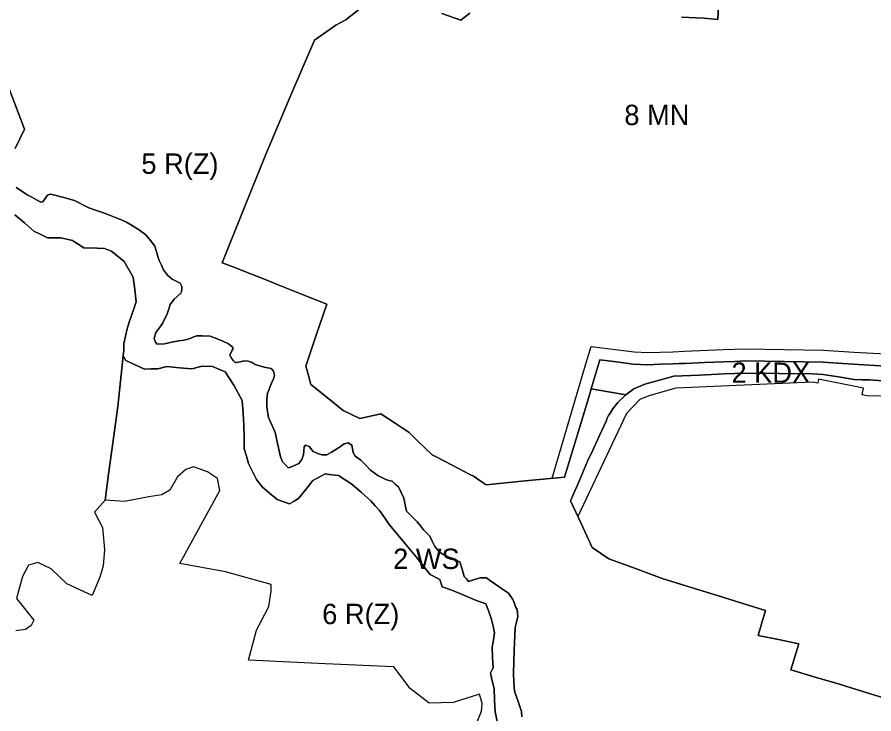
# Model space of a CAD drawing. Extents: x -294445 to -292055, y 21869 to 23693.
# Drawn here: x -293995.9 to -293575, y 22129.5 to 22471.6 of the extents above; entities that cross this region are included whole.
import ezdxf

# ---------------------------------------------------------------- set-up
doc = ezdxf.new("R2010")
doc.units = 0
for name, color, linetype in [('linie_rozgraniczajace', 7, 'Continuous'), ('linie_zabudowy_nieprzekraczalne', 7, 'Continuous'), ('oznaczenia_przeznaczen', 7, 'Continuous')]:
    doc.layers.add(name, color=color, linetype=linetype)

msp = doc.modelspace()

# ---------------------------------------------------------------- linework, layer by layer
at = {"layer": 'linie_rozgraniczajace'}
for points in [[(-293669.485, 22471.61), (-293662.035, 22471.25), (-293658.31, 22471.07), (-293651.55, 22470.39), (-293650.913, 22483.44)], [(-293650.913, 22483.44), (-293651.55, 22470.39), (-293658.31, 22471.07), (-293662.035, 22471.25), (-293669.485, 22471.61)], [(-293895.099, 22350.989), (-293884.475, 22377.411), (-293873.851, 22403.833), (-293861.856, 22432.017), (-293849.86, 22460.2), (-293839.31, 22467.62), (-293834.33, 22470.28), (-293823.35, 22478.86)], [(-293823.35, 22478.86), (-293834.33, 22470.28), (-293839.31, 22467.62), (-293849.86, 22460.2), (-293861.856, 22432.017), (-293873.851, 22403.833), (-293884.475, 22377.411), (-293895.099, 22350.989), (-293888.998, 22348.592), (-293882.896, 22346.194), (-293875.674, 22343.307), (-293868.451, 22340.419), (-293856.133, 22335.494), (-293843.814, 22330.57), (-293848.947, 22315.346), (-293854.08, 22300.122), (-293852.804, 22295.615), (-293851.529, 22291.107), (-293843.613, 22284.726), (-293835.696, 22278.345), (-293831.615, 22276.438), (-293827.535, 22274.532), (-293822.327, 22275.651), (-293817.12, 22276.77), (-293810.2, 22272.17), (-293803.28, 22267.57), (-293799.36, 22263.72), (-293791.97, 22256.66), (-293789.09, 22255.16), (-293786.21, 22253.66), (-293778.755, 22249.805), (-293773.734, 22247.209), (-293771.3, 22245.95), (-293768.39, 22243.92), (-293765.48, 22241.89), (-293746.225, 22243.815), (-293726.97, 22245.74), (-293721.229, 22264.536), (-293715.487, 22283.331), (-293714.654, 22286.159), (-293713.821, 22288.988), (-293696.76, 22286.12), (-293700.82, 22282.26), (-293701.99, 22280.77), (-293703.16, 22279.28), (-293704.235, 22277.645), (-293705.31, 22276.01), (-293705.935, 22274.63), (-293706.56, 22273.25), (-293709.81, 22266.105), (-293713.06, 22258.96), (-293715.62, 22253.54), (-293719.8, 22243.785), (-293723.98, 22234.03), (-293718.67, 22222.545), (-293713.36, 22211.06)], [(-293787.308, 22473.333), (-293777.927, 22469.988), (-293773.45, 22473.55)], [(-293773.45, 22473.55), (-293777.927, 22469.988), (-293787.308, 22473.333)], [(-293996.895, 22407.1), (-293992.35, 22416.5), (-294000.24, 22437.73)], [(-294000.24, 22437.73), (-293992.35, 22416.5), (-293996.895, 22407.1)], [(-293967.78, 22381.47), (-293972.925, 22382.925), (-293978.07, 22384.38), (-293979.68, 22384.64), (-293980.99, 22384.14), (-293983.19, 22380.88), (-293984.21, 22380.78), (-293986.3, 22381.85), (-293988.6, 22383.115), (-293990.9, 22384.38), (-293993.655, 22386.175), (-293996.41, 22387.97)], [(-293996.41, 22387.97), (-293993.655, 22386.175), (-293990.9, 22384.38), (-293988.6, 22383.115), (-293986.3, 22381.85), (-293984.21, 22380.78), (-293983.19, 22380.88), (-293980.99, 22384.14), (-293979.68, 22384.64), (-293978.07, 22384.38), (-293972.925, 22382.925), (-293967.78, 22381.47), (-293960.65, 22377.98), (-293956.825, 22376.64), (-293953, 22375.3), (-293950.51, 22374.355), (-293948.02, 22373.41), (-293945.055, 22372.135), (-293942.09, 22370.86), (-293938.91, 22368.895), (-293935.73, 22366.93), (-293932.72, 22364.71), (-293930.45, 22361.87)], [(-293845.96, 22256.68), (-293847.85, 22257.1), (-293850.38, 22258.35), (-293852.46, 22260.67), (-293854.15, 22261.33), (-293854.92, 22260.61), (-293855.04, 22258.645), (-293855.16, 22256.68), (-293856.01, 22254.27), (-293857.5, 22252.45), (-293861.13, 22250.73), (-293862.74, 22250.27), (-293864.095, 22251.76), (-293865.45, 22253.25), (-293866.54, 22255.6), (-293867.81, 22261.63), (-293869.08, 22267.66), (-293870.76, 22271.315), (-293872.44, 22274.97), (-293872.826, 22277.985), (-293873.15, 22280.51), (-293873.145, 22282.005), (-293873.14, 22283.5), (-293872.81, 22286.84), (-293872.271, 22288.356), (-293871.534, 22290.215), (-293870.91, 22291.77), (-293869.96, 22293.94), (-293869.5, 22295.72), (-293869.93, 22297.66), (-293871.07, 22299.02), (-293874.55, 22299.68), (-293878.89, 22300.93), (-293880.43, 22302), (-293882.35, 22302.68), (-293884.33, 22302.8), (-293886.235, 22302.365), (-293888.14, 22301.93), (-293888.82, 22302.02), (-293889.62, 22302.75), (-293890.537, 22304.187), (-293891.454, 22305.624), (-293890.27, 22307.97), (-293889.78, 22308.82), (-293890.32, 22309.72), (-293892.06, 22311.16), (-293894.835, 22312.41), (-293897.61, 22313.66), (-293901.08, 22314.97), (-293904.95, 22315.15), (-293907.57, 22315), (-293909.03, 22314.59), (-293911.3, 22313.6), (-293913.77, 22313.02), (-293916.48, 22312.67), (-293919.945, 22311.905), (-293923.41, 22311.14), (-293927.04, 22310.97), (-293927.99, 22311.92), (-293928.3, 22312.86), (-293928.61, 22313.8), (-293927.7, 22316.67), (-293926.06, 22318.89), (-293924.42, 22321.11), (-293923.415, 22323.28), (-293922.41, 22325.45), (-293921.91, 22326.825), (-293921.41, 22328.2), (-293921.095, 22329.29), (-293920.78, 22330.38), (-293918.78, 22333.11), (-293917.14, 22334.6), (-293915.5, 22336.09), (-293915.07, 22336.6), (-293915.063, 22336.894), (-293915.04, 22337.915), (-293915.01, 22339.23), (-293915.73, 22340.94), (-293917.46, 22341.68), (-293919.75, 22342.87), (-293922.01, 22344.82), (-293922.99, 22346.16), (-293923.97, 22347.5), (-293925.035, 22349.775), (-293926.1, 22352.05), (-293926.7, 22353.97), (-293927.3, 22355.89), (-293928.18, 22359.03), (-293930.45, 22361.87), (-293932.72, 22364.71), (-293935.73, 22366.93), (-293938.91, 22368.895), (-293942.09, 22370.86), (-293945.055, 22372.135), (-293948.02, 22373.41), (-293950.51, 22374.355), (-293953, 22375.3), (-293956.825, 22376.64), (-293960.65, 22377.98), (-293967.78, 22381.47)], [(-293997.05, 22374.42), (-293992.35, 22370.48), (-293987.65, 22366.54), (-293984.295, 22364.845), (-293980.94, 22363.15), (-293977.65, 22363.15), (-293974.36, 22363.15), (-293971.5, 22362.53), (-293968.64, 22361.91), (-293967.265, 22360.975), (-293965.89, 22360.04), (-293963.16, 22358.32), (-293956.56, 22358.18), (-293953.02, 22357.92), (-293951.285, 22357.305), (-293949.55, 22356.69), (-293943.32, 22351.62), (-293938.81, 22343.88), (-293938.085, 22337.845), (-293937.36, 22331.81), (-293938.56, 22328.385), (-293940.78, 22321.725), (-293941.8, 22318.49), (-293942.63, 22314.92), (-293943.46, 22311.35), (-293943.445, 22309.58), (-293943.43, 22307.81), (-293943.77, 22305.2), (-293945.135, 22292.815), (-293946.5, 22280.43), (-293948.72, 22263.75), (-293950.94, 22247.07), (-293952.6, 22234.39), (-293957.87, 22228.5), (-293954.02, 22221), (-293952.98, 22210.24), (-293953.55, 22202.1), (-293955.32, 22196.62), (-293959.09, 22187.56), (-293971.46, 22193.23), (-293979.15, 22200.65), (-293985.7, 22203.83), (-293990.37, 22202.43), (-293993.27, 22196.94), (-293996.21, 22186.18), (-293987.7, 22175.54), (-293989.03, 22172.85), (-293991.83, 22170.9), (-293996.59, 22170.18)], [(-293762.725, 22150.705), (-293762.09, 22152.03), (-293762.28, 22157.155), (-293762.47, 22162.28), (-293761.92, 22165.745), (-293761.37, 22169.21), (-293762.075, 22172.53), (-293762.78, 22175.85), (-293764.16, 22179.695), (-293765.54, 22183.54), (-293770.7, 22185.36), (-293776.489, 22187.758), (-293782.278, 22190.156), (-293787.01, 22191.78), (-293788.22, 22195.38), (-293792.97, 22197.93), (-293796.39, 22202.205), (-293799.81, 22206.48), (-293806.425, 22214.445), (-293813.04, 22222.41), (-293815.415, 22225.845), (-293817.79, 22229.28), (-293819.915, 22231.66), (-293822.04, 22234.04), (-293826.77, 22238.145), (-293831.5, 22242.25), (-293834.755, 22244.345), (-293838.01, 22246.44), (-293841.265, 22246.9), (-293844.52, 22247.36), (-293847.55, 22245.715), (-293850.58, 22244.07), (-293854.095, 22239.65), (-293857.61, 22235.23), (-293859.865, 22233.9), (-293862.12, 22232.57), (-293868.13, 22234.77), (-293871.825, 22237.865), (-293875.52, 22240.96), (-293878.25, 22244.46), (-293880.25, 22248.415), (-293882.25, 22252.37), (-293883.265, 22256.02), (-293884.28, 22259.67), (-293884.37, 22265.325), (-293884.46, 22270.98), (-293884.895, 22277.125), (-293885.33, 22283.27), (-293889.44, 22290.81), (-293893.66, 22297.32), (-293899.91, 22300), (-293905, 22300.15), (-293910, 22298.83), (-293916.145, 22299.425), (-293922.29, 22300.02), (-293926.79, 22298.92), (-293930.02, 22298.8), (-293933.25, 22298.68), (-293937.87, 22300.805), (-293942.49, 22302.93), (-293943.77, 22305.2), (-293943.43, 22307.81), (-293943.445, 22309.58), (-293943.46, 22311.35), (-293942.63, 22314.92), (-293941.8, 22318.49), (-293940.78, 22321.725), (-293938.56, 22328.385), (-293937.36, 22331.81), (-293938.085, 22337.845), (-293938.81, 22343.88), (-293943.32, 22351.62), (-293949.55, 22356.69), (-293951.285, 22357.305), (-293953.02, 22357.92), (-293956.56, 22358.18), (-293963.16, 22358.32), (-293965.89, 22360.04), (-293967.265, 22360.975), (-293968.64, 22361.91), (-293971.5, 22362.53), (-293974.36, 22363.15), (-293977.65, 22363.15), (-293980.94, 22363.15), (-293984.295, 22364.845), (-293987.65, 22366.54), (-293992.35, 22370.48), (-293997.05, 22374.42)], [(-293930.45, 22361.87), (-293928.18, 22359.03), (-293927.3, 22355.89), (-293926.7, 22353.97), (-293926.1, 22352.05), (-293925.035, 22349.775), (-293923.97, 22347.5), (-293922.99, 22346.16), (-293922.01, 22344.82), (-293919.75, 22342.87), (-293917.46, 22341.68), (-293915.73, 22340.94), (-293915.01, 22339.23), (-293915.04, 22337.915), (-293915.063, 22336.894), (-293915.07, 22336.6), (-293915.5, 22336.09), (-293917.14, 22334.6), (-293918.78, 22333.11), (-293920.78, 22330.38), (-293921.095, 22329.29), (-293921.41, 22328.2), (-293921.91, 22326.825), (-293922.41, 22325.45), (-293923.415, 22323.28), (-293924.42, 22321.11), (-293926.06, 22318.89), (-293927.7, 22316.67), (-293928.61, 22313.8), (-293928.3, 22312.86), (-293927.99, 22311.92), (-293927.04, 22310.97), (-293923.41, 22311.14), (-293919.945, 22311.905), (-293916.48, 22312.67), (-293913.77, 22313.02), (-293911.3, 22313.6), (-293909.03, 22314.59), (-293907.57, 22315), (-293904.95, 22315.15), (-293901.08, 22314.97), (-293897.61, 22313.66), (-293894.835, 22312.41), (-293892.06, 22311.16), (-293890.32, 22309.72), (-293889.78, 22308.82), (-293890.27, 22307.97), (-293891.454, 22305.624), (-293890.537, 22304.187), (-293889.62, 22302.75), (-293888.82, 22302.02), (-293888.14, 22301.93), (-293886.235, 22302.365), (-293884.33, 22302.8), (-293882.35, 22302.68), (-293880.43, 22302), (-293878.89, 22300.93), (-293874.55, 22299.68), (-293871.07, 22299.02), (-293869.93, 22297.66), (-293869.5, 22295.72), (-293869.96, 22293.94), (-293870.91, 22291.77), (-293871.534, 22290.215), (-293872.271, 22288.356), (-293872.81, 22286.84), (-293873.14, 22283.5), (-293873.145, 22282.005), (-293873.15, 22280.51), (-293872.826, 22277.985), (-293872.44, 22274.97), (-293870.76, 22271.315), (-293869.08, 22267.66), (-293867.81, 22261.63), (-293866.54, 22255.6), (-293865.45, 22253.25), (-293864.095, 22251.76), (-293862.74, 22250.27), (-293861.13, 22250.73), (-293857.5, 22252.45), (-293856.01, 22254.27), (-293855.16, 22256.68), (-293855.04, 22258.645), (-293854.92, 22260.61), (-293854.15, 22261.33), (-293852.46, 22260.67), (-293850.38, 22258.35), (-293847.85, 22257.1), (-293845.96, 22256.68), (-293843.79, 22256.68), (-293841.48, 22257.87), (-293838.993, 22259.409), (-293837.085, 22260.75), (-293835.15, 22262.11), (-293833.27, 22262.5), (-293831.52, 22261.31), (-293831.175, 22259.54), (-293830.83, 22257.77), (-293829.78, 22256.01), (-293827.08, 22254.02)], [(-293569.2, 22300.225), (-293585.2, 22301.11), (-293592.594, 22301.599), (-293599.987, 22302.087), (-293618.988, 22302.408), (-293637.989, 22302.73), (-293643.346, 22302.538), (-293648.704, 22302.345), (-293658.197, 22301.952), (-293667.69, 22301.558), (-293670.595, 22301.43), (-293673.501, 22301.302), (-293679.746, 22301.085), (-293685.99, 22300.869), (-293689.595, 22301.035), (-293693.2, 22301.2), (-293701.404, 22302.229), (-293709.609, 22303.258), (-293713.821, 22288.988), (-293714.654, 22286.159), (-293715.487, 22283.331), (-293721.229, 22264.536), (-293726.97, 22245.74), (-293746.225, 22243.815), (-293765.48, 22241.89), (-293768.39, 22243.92), (-293771.3, 22245.95), (-293773.734, 22247.209), (-293778.755, 22249.805), (-293786.21, 22253.66), (-293789.09, 22255.16), (-293791.97, 22256.66), (-293799.36, 22263.72), (-293803.28, 22267.57), (-293810.2, 22272.17), (-293817.12, 22276.77), (-293822.327, 22275.651), (-293827.535, 22274.532), (-293831.615, 22276.438), (-293835.696, 22278.345), (-293843.613, 22284.726), (-293851.529, 22291.107), (-293852.804, 22295.615), (-293854.08, 22300.122), (-293848.947, 22315.346), (-293843.814, 22330.57), (-293856.133, 22335.494), (-293868.451, 22340.419), (-293875.674, 22343.307), (-293882.896, 22346.194), (-293888.998, 22348.592), (-293895.099, 22350.989)], [(-293952.6, 22234.39), (-293950.94, 22247.07), (-293948.72, 22263.75), (-293946.5, 22280.43), (-293945.135, 22292.815), (-293943.77, 22305.2), (-293942.49, 22302.93), (-293937.87, 22300.805), (-293933.25, 22298.68), (-293930.02, 22298.8), (-293926.79, 22298.92), (-293922.29, 22300.02), (-293916.145, 22299.425), (-293910, 22298.83), (-293905, 22300.15), (-293899.91, 22300), (-293893.66, 22297.32), (-293889.44, 22290.81), (-293885.33, 22283.27), (-293884.895, 22277.125), (-293884.46, 22270.98), (-293884.37, 22265.325), (-293884.28, 22259.67), (-293883.265, 22256.02), (-293882.25, 22252.37), (-293880.25, 22248.415), (-293878.25, 22244.46), (-293875.52, 22240.96), (-293871.825, 22237.865), (-293868.13, 22234.77), (-293862.12, 22232.57), (-293859.865, 22233.9), (-293857.61, 22235.23), (-293854.095, 22239.65), (-293850.58, 22244.07), (-293847.55, 22245.715), (-293844.52, 22247.36), (-293841.265, 22246.9), (-293838.01, 22246.44), (-293834.755, 22244.345), (-293831.5, 22242.25), (-293826.77, 22238.145), (-293822.04, 22234.04), (-293819.915, 22231.66), (-293817.79, 22229.28), (-293815.415, 22225.845), (-293813.04, 22222.41), (-293806.425, 22214.445), (-293799.81, 22206.48), (-293796.39, 22202.205), (-293792.97, 22197.93), (-293788.22, 22195.38), (-293787.01, 22191.78), (-293782.278, 22190.156), (-293776.489, 22187.758), (-293770.7, 22185.36), (-293765.54, 22183.54), (-293764.16, 22179.695), (-293762.78, 22175.85), (-293762.075, 22172.53), (-293761.37, 22169.21), (-293761.92, 22165.745), (-293762.47, 22162.28), (-293762.28, 22157.155), (-293762.09, 22152.03), (-293762.725, 22150.705), (-293763.36, 22149.38), (-293762.46, 22145.65), (-293761.56, 22141.92), (-293761.31, 22136.165), (-293761.06, 22130.41), (-293759.355, 22122.81)], [(-293561.8, 22292.265), (-293577.14, 22293.43), (-293580.92, 22293.525), (-293584.7, 22293.62), (-293592.35, 22294.875), (-293600, 22296.13), (-293602.555, 22296.24), (-293605.11, 22296.35), (-293621.513, 22296.539), (-293637.916, 22296.729), (-293643.193, 22296.539), (-293648.47, 22296.35), (-293660.859, 22295.828), (-293673.249, 22295.307), (-293680.364, 22293.298), (-293687.48, 22291.29), (-293692.9, 22288.98), (-293696.76, 22286.12), (-293713.821, 22288.988), (-293709.609, 22303.258), (-293701.404, 22302.229), (-293693.2, 22301.2), (-293689.595, 22301.035), (-293685.99, 22300.869), (-293679.746, 22301.085), (-293673.501, 22301.302), (-293670.595, 22301.43), (-293667.69, 22301.558), (-293658.197, 22301.952), (-293648.704, 22302.345), (-293643.346, 22302.538), (-293637.989, 22302.73), (-293618.988, 22302.408), (-293599.987, 22302.087), (-293592.594, 22301.599), (-293585.2, 22301.11), (-293569.2, 22300.225)], [(-293723.98, 22234.03), (-293719.8, 22243.785), (-293715.62, 22253.54), (-293713.06, 22258.96), (-293709.81, 22266.105), (-293706.56, 22273.25), (-293705.935, 22274.63), (-293705.31, 22276.01), (-293704.235, 22277.645), (-293703.16, 22279.28), (-293701.99, 22280.77), (-293700.82, 22282.26), (-293696.76, 22286.12), (-293692.9, 22288.98), (-293687.48, 22291.29), (-293680.364, 22293.298), (-293673.249, 22295.307), (-293660.859, 22295.828), (-293648.47, 22296.35), (-293643.193, 22296.539), (-293637.916, 22296.729), (-293621.513, 22296.539), (-293605.11, 22296.35), (-293602.555, 22296.24), (-293600, 22296.13), (-293592.35, 22294.875), (-293584.7, 22293.62), (-293580.92, 22293.525), (-293577.14, 22293.43), (-293561.8, 22292.265)], [(-293747.925, 22128.055), (-293748.15, 22130.56), (-293749.805, 22135.58), (-293751.46, 22140.6), (-293751.775, 22144.98), (-293752.09, 22149.36), (-293751.655, 22160.61), (-293751.22, 22171.86), (-293750.515, 22174.525), (-293749.81, 22177.19), (-293750.005, 22178.925), (-293750.2, 22180.66), (-293750.83, 22181.74), (-293751.6, 22183.705), (-293752.37, 22185.67), (-293754.54, 22188.76), (-293757.881, 22191.056), (-293761.221, 22193.352), (-293763.286, 22194.771), (-293765.35, 22196.19), (-293768.24, 22196.26), (-293771.165, 22195.375), (-293774.09, 22194.49), (-293775.155, 22195.715), (-293776.22, 22196.94), (-293777.3, 22200.505), (-293778.38, 22204.07), (-293782.645, 22205.985), (-293786.91, 22207.9), (-293787.775, 22208.59), (-293788.64, 22209.28), (-293789.635, 22210.48), (-293790.63, 22211.68), (-293791.915, 22214.22), (-293793.2, 22216.76), (-293794.74, 22218.275), (-293796.28, 22219.79), (-293797.785, 22221.78), (-293799.29, 22223.77), (-293801.98, 22226.375), (-293804.67, 22228.98), (-293805.29, 22232.135), (-293805.91, 22235.29), (-293807.195, 22238.095), (-293808.48, 22240.9), (-293810.095, 22242.32), (-293811.71, 22243.74), (-293813.19, 22244.105), (-293814.67, 22244.47), (-293816.68, 22245.45), (-293818.69, 22246.43), (-293820.445, 22247.785), (-293822.2, 22249.14), (-293824.64, 22251.58), (-293827.08, 22254.02), (-293829.78, 22256.01), (-293830.83, 22257.77), (-293831.175, 22259.54), (-293831.52, 22261.31), (-293833.27, 22262.5), (-293835.15, 22262.11), (-293837.085, 22260.75), (-293838.993, 22259.409), (-293841.48, 22257.87), (-293843.79, 22256.68), (-293845.96, 22256.68)], [(-293773.31, 22117.04), (-293767.82, 22130.76), (-293767.37, 22134.49), (-293768.73, 22139.17), (-293781.71, 22135.03), (-293793.5, 22134.76), (-293802.83, 22141.83), (-293810.79, 22152.49), (-293844.53, 22153.94), (-293858.27, 22154.66), (-293882.26, 22155.89), (-293878.23, 22170.56), (-293872.22, 22182.19), (-293871.15, 22189.72), (-293871.02, 22193), (-293893.47, 22199.13), (-293916, 22203.3), (-293896.29, 22239.13), (-293897.38, 22245.09), (-293902.33, 22248.33), (-293909.28, 22250.79), (-293912.99, 22249.45), (-293917.04, 22245.87), (-293920.82, 22239.3), (-293924.85, 22236.98), (-293931.21, 22235.95), (-293943.18, 22233.65), (-293952.6, 22234.39)], [(-293827.08, 22254.02), (-293824.64, 22251.58), (-293822.2, 22249.14), (-293820.445, 22247.785), (-293818.69, 22246.43), (-293816.68, 22245.45), (-293814.67, 22244.47), (-293813.19, 22244.105), (-293811.71, 22243.74), (-293810.095, 22242.32), (-293808.48, 22240.9), (-293807.195, 22238.095), (-293805.91, 22235.29), (-293805.29, 22232.135), (-293804.67, 22228.98), (-293801.98, 22226.375), (-293799.29, 22223.77), (-293797.785, 22221.78), (-293796.28, 22219.79), (-293794.74, 22218.275), (-293793.2, 22216.76), (-293791.915, 22214.22), (-293790.63, 22211.68), (-293789.635, 22210.48), (-293788.64, 22209.28), (-293787.775, 22208.59), (-293786.91, 22207.9), (-293782.645, 22205.985), (-293778.38, 22204.07), (-293777.3, 22200.505), (-293776.22, 22196.94), (-293775.155, 22195.715), (-293774.09, 22194.49), (-293771.165, 22195.375), (-293768.24, 22196.26), (-293765.35, 22196.19), (-293763.286, 22194.771), (-293761.221, 22193.352), (-293757.881, 22191.056), (-293754.54, 22188.76), (-293752.37, 22185.67), (-293751.6, 22183.705), (-293750.83, 22181.74), (-293750.2, 22180.66), (-293750.005, 22178.925), (-293749.81, 22177.19), (-293750.515, 22174.525), (-293751.22, 22171.86), (-293751.655, 22160.61), (-293752.09, 22149.36), (-293751.775, 22144.98), (-293751.46, 22140.6), (-293749.805, 22135.58), (-293748.15, 22130.56), (-293747.925, 22128.055)], [(-293563.68, 22135.29), (-293577.79, 22139.63), (-293591.9, 22143.97), (-293603.803, 22147.516), (-293615.705, 22151.062), (-293611.8, 22163.84), (-293621.815, 22165.89), (-293631.83, 22167.94), (-293630.013, 22174.113), (-293628.196, 22180.286), (-293639.768, 22183.883), (-293651.34, 22187.48), (-293665.17, 22191.74), (-293679, 22196), (-293692.115, 22200.785), (-293705.23, 22205.57), (-293709.295, 22208.315), (-293713.36, 22211.06), (-293718.67, 22222.545), (-293723.98, 22234.03)], [(-293713.36, 22211.06), (-293709.295, 22208.315), (-293705.23, 22205.57), (-293692.115, 22200.785), (-293679, 22196), (-293665.17, 22191.74), (-293651.34, 22187.48), (-293639.768, 22183.883), (-293628.196, 22180.286), (-293630.013, 22174.113), (-293631.83, 22167.94), (-293621.815, 22165.89), (-293611.8, 22163.84), (-293615.705, 22151.062), (-293603.803, 22147.516), (-293591.9, 22143.97), (-293577.79, 22139.63), (-293563.68, 22135.29)], [(-293759.355, 22122.81), (-293761.06, 22130.41), (-293761.31, 22136.165), (-293761.56, 22141.92), (-293762.46, 22145.65), (-293763.36, 22149.38), (-293762.725, 22150.705)]]:
    msp.add_lwpolyline(points, dxfattribs=at)
at = {"layer": 'linie_zabudowy_nieprzekraczalne'}
for points in [[(-293732.989, 22245.138), (-293716.444, 22301.322), (-293713.911, 22309.844), (-293692.688, 22307.183), (-293685.957, 22306.874), (-293673.737, 22307.297), (-293667.947, 22307.552), (-293648.936, 22308.341), (-293638.046, 22308.732), (-293599.739, 22308.084), (-293584.837, 22307.099), (-293553.076, 22305.342)], [(-293508.701, 22285.12), (-293578.4, 22285.62), (-293580.735, 22286.083), (-293580.083, 22289.369), (-293602.122, 22293.744), (-293602.475, 22291.91), (-293605.037, 22292.402), (-293672.295, 22289.342), (-293685.481, 22285.62), (-293689.897, 22283.738), (-293696.548, 22277.009), (-293720.459, 22226.415)]]:
    msp.add_lwpolyline(points, dxfattribs=at)

# ---------------------------------------------------------------- texts
at = {"layer": 'oznaczenia_przeznaczen'}
for s, p in [('8 MN', (-293697.569, 22418.534)), ('5 R(Z)', (-293934.854, 22394.607)), ('2 KDX', (-293644.912, 22291.997)), ('2 WS', (-293811.155, 22200.589)), ('6 R(Z)', (-293845.999, 22173.499))]:
    msp.add_text(s, height=10, dxfattribs=at).set_placement(p)

doc.saveas('drawing.dxf')
